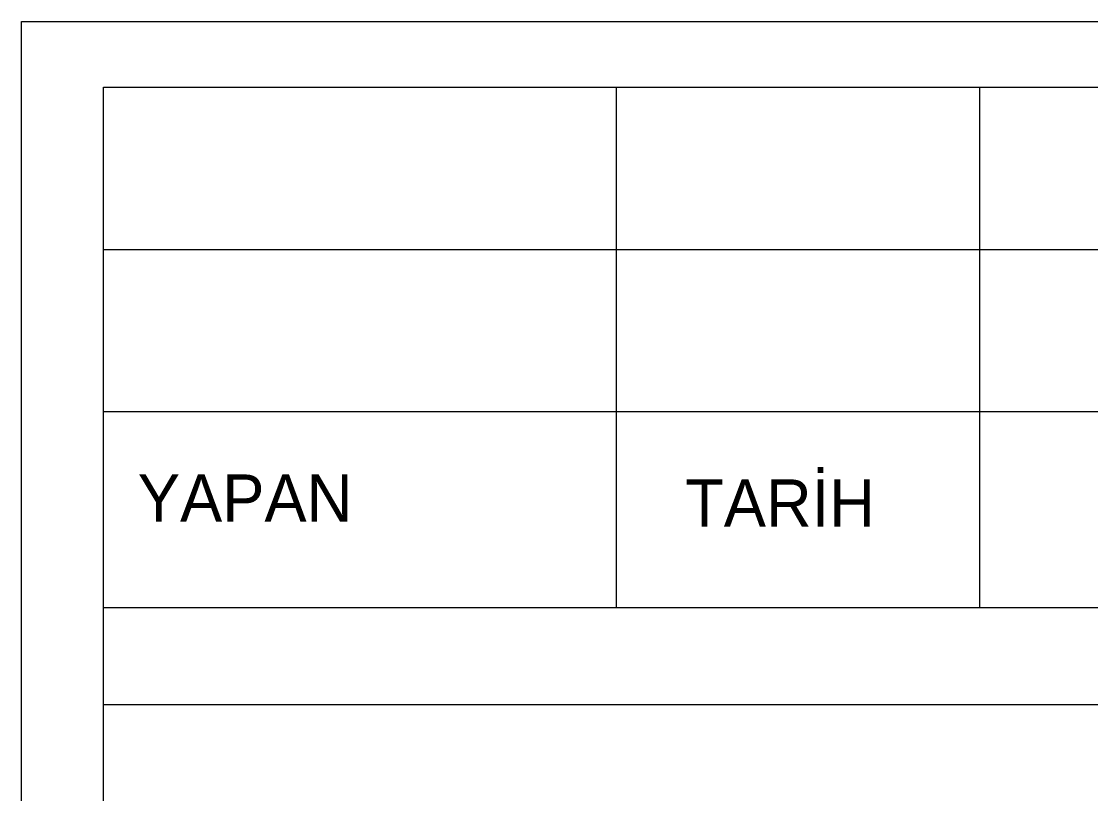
# Model space of a CAD drawing. Extents: x -17 to 1145, y -10 to 821.
# Drawn here: x 960 to 1005.19, y 254.33 to 287 of the extents above; entities that cross this region are included whole.
import ezdxf

# ---------------------------------------------------------------- set-up
doc = ezdxf.new("R2010")
doc.units = 0
for name, color, linetype in [('Level 1', 7, 'Continuous'), ('Level 6', 7, 'Continuous'), ('Level 7', 7, 'Continuous')]:
    doc.layers.add(name, color=color, linetype=linetype)

msp = doc.modelspace()

# ---------------------------------------------------------------- linework, layer by layer
at = {"layer": 'Level 1'}
for p, q in [((960, 287), (1135, 287)), ((960, 0), (960, 287))]:
    msp.add_line(p, q, dxfattribs=at)
at = {"layer": 'Level 6'}
for p, q in [((963.472, 260.692), (963.472, 284.215)), ((963.472, 284.215), (1131.447, 284.215)), ((963.472, 260.692), (963.472, 284.215)), ((963.472, 260.692), (963.472, 284.215)), ((963.472, 284.215), (1131.447, 284.215)), ((963.472, 260.692), (963.472, 284.215)), ((963.472, 260.692), (963.472, 284.215)), ((963.472, 284.215), (1131.447, 284.215)), ((963.472, 260.692), (963.472, 284.215)), ((963.472, 260.692), (963.472, 284.215)), ((963.472, 284.215), (1131.447, 284.215)), ((963.472, 260.692), (963.472, 284.215)), ((966.601, 284.215), (1128.318, 284.215)), ((966.601, 284.215), (1128.318, 284.215)), ((966.601, 284.215), (1128.318, 284.215)), ((966.601, 284.215), (1128.318, 284.215)), ((966.601, 284.215), (1128.318, 284.215)), ((966.601, 284.215), (1128.318, 284.215)), ((966.601, 284.215), (1128.318, 284.215)), ((966.601, 284.215), (1128.318, 284.215)), ((985.153, 262.2), (985.153, 284.215)), ((985.153, 262.2), (985.153, 284.215)), ((985.153, 262.2), (985.153, 284.215)), ((985.153, 262.2), (985.153, 284.215)), ((1000.515, 262.2), (1000.515, 284.215)), ((1000.515, 262.2), (1000.515, 284.215)), ((1000.515, 262.2), (1000.515, 284.215)), ((1000.515, 262.2), (1000.515, 284.215)), ((963.472, 277.351), (1131.447, 277.351)), ((963.472, 277.351), (1131.447, 277.351)), ((963.472, 277.351), (1131.447, 277.351)), ((963.472, 277.351), (1131.447, 277.351)), ((963.472, 270.492), (1131.447, 270.492)), ((963.472, 270.492), (1131.447, 270.492)), ((963.472, 270.492), (1131.447, 270.492)), ((963.472, 270.492), (1131.447, 270.492)), ((963.472, 4.971), (963.472, 267.902)), ((963.472, 262.2), (1131.447, 262.2)), ((963.472, 262.2), (1131.447, 262.2)), ((963.472, 262.2), (1131.447, 262.2)), ((963.472, 262.2), (1131.447, 262.2)), ((963.472, 258.106), (1131.447, 258.106)), ((963.472, 258.106), (1131.447, 258.106)), ((963.472, 258.106), (1131.447, 258.106)), ((963.472, 258.106), (1131.447, 258.106))]:
    msp.add_line(p, q, dxfattribs=at)

# ---------------------------------------------------------------- texts
at = {"layer": 'Level 7'}
for s, p in [('TARİH', (988.054, 265.622)), ('YAPAN', (964.921, 265.832))]:
    msp.add_text(s, height=2, dxfattribs=at).set_placement(p)

doc.saveas('drawing.dxf')
